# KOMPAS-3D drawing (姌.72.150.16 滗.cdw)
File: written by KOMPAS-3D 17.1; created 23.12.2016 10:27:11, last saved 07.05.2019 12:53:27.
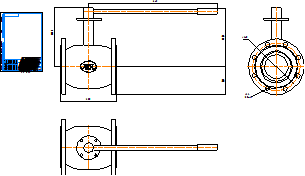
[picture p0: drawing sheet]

Sheet 1: A4, portrait

Title block, sheet 1: name: КШ.72.150.16 фф; material: Внимание! Данный продукт является объектом авторского права ООО «Торговый Дом АДЛ». / Запрещается изменение, копирование, распространение / (в том числе путем копирования на другие сайты и ресурсы в Интернете) / или любое иное использование информации и объектов без предварительного / согласия правообладателя (ООО «Торговый Дом АДЛ»).; sheets: 1; organisation: ООО "Торговый дом АДЛ"; sheet format: A4; stored path: C:\Users\tra\Desktop\2д чертежи\Шаровые краны БИВАЛ\КШ_Бивал_серия_72\KOMPAS_2D\КШ.72.150.16 фф.cdw

Views: Спереди 4, Проекционный вид 5, Проекционный вид 6
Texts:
  Klimkovich
  ADL
Dimensions and other numbers on the sheet: 280; 645; 295,6; 291,6; 140; 240; 22; 8 Отв.; 1:1; 1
